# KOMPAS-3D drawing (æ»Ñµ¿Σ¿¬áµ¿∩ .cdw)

Referenced files: Спецификация 1.cdw
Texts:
  Призма  раздвижная Спецификация
  ХХХХ.ХХ.ХХ.00 СБ
  Документация
  Детали
  Корпус
  Призма
  Винт
  Ручка
  Шайба
  раздвижная
  Планка
  Стандартные изделия
  Винт 2М8х25.58
  ГОСТ 1491-80
  Винт 2М12х30.58
Dimensions and other numbers on the sheet: 1:1; 1; 2; 3; 4; 5; 6; 7; 8; 9; 10; 0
